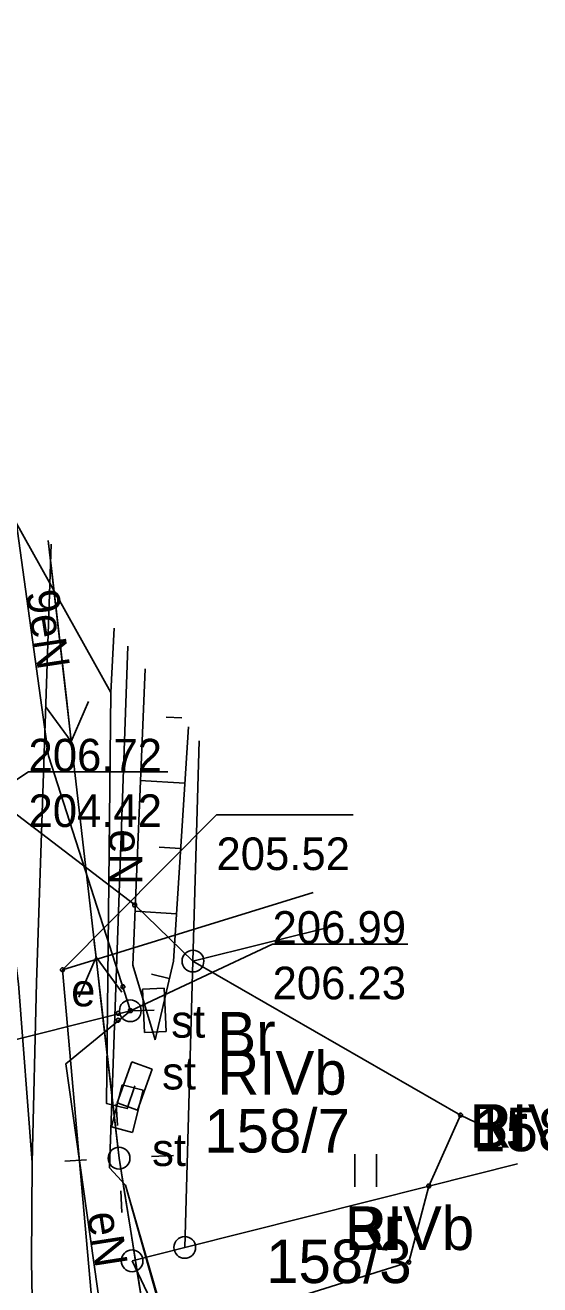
# Model space of a CAD drawing. Extents: x 6512400 to 6513200, y 6022500 to 6022750.
# Drawn here: x 6512853.97 to 6512865.8, y 6022634.38 to 6022663.33 of the extents above; entities that cross this region are included whole.
import ezdxf

# ---------------------------------------------------------------- set-up
doc = ezdxf.new("R2010")
doc.units = 0
for name, color, linetype in [('202-punkt graniczny', 7, 'Continuous'), ('203-punkt graniczny', 7, 'Continuous'), ('209-oznaczenie konturu klasyfikacyjnego', 7, 'Continuous'), ('210-oznaczenie konturu użytku gruntowego', 7, 'Continuous'), ('211-numer działki ewidencyjnej', 7, 'Continuous'), ('217-kontur klasyfikacyjny', 7, 'Continuous'), ('218-kontur użytku gruntowego', 7, 'Continuous'), ('219-działka ewidencyjna', 7, 'Continuous'), ('820-Skarpa nieumocniona', 7, 'Continuous'), ('823-Szczyt skarpy nieumocninej', 7, 'Continuous'), ('824-Podnóże skarpy nieumocninej', 7, 'Continuous'), ('940-Trawnik symb. poj.', 7, 'Continuous'), ('chodnik (powierzchnia)', 7, 'Continuous'), ('krawężnik (linia)', 7, 'Continuous'), ('latarnia na słupie lub maszcie (punkt)', 7, 'Continuous'), ('ogrodzenie trwałe (linia)', 7, 'Continuous'), ('przewód elektroenergetyczny (linia)', 7, 'Continuous'), ('przewód elektroenergetyczny (linia)-Atr1', 7, 'Continuous'), ('przewód elektroenergetyczny niskiego napięcia (linia)', 7, 'Continuous'), ('przewód elektroenergetyczny niskiego napięcia (linia) - symbol', 7, 'Continuous'), ('przewód gazowy (linia)', 7, 'Continuous'), ('punkt o określonej wysokości (sieć ciepłownicza)-Atr2', 7, 'Continuous'), ('punkt o określonej wysokości (sieć ciepłownicza)-Atr3', 7, 'Continuous'), ('punkt o określonej wysokości (sieć elektroenergetyczna)', 7, 'Continuous'), ('punkt o określonej wysokości (sieć elektroenergetyczna)-Atr2', 7, 'Continuous'), ('punkt o określonej wysokości (sieć elektroenergetyczna)-Atr3', 7, 'Continuous'), ('punkt o określonej wysokości (sieć gazowa)', 7, 'Continuous'), ('punkt o określonej wysokości (sieć gazowa)-Atr2', 7, 'Continuous'), ('punkt o określonej wysokości (sieć gazowa)-Atr3', 7, 'Continuous'), ('szafa elektroenergetyczna (punkt)', 7, 'Continuous'), ('szafa elektroenergetyczna (punkt)-Atr17', 7, 'Continuous'), ('słup (punkt)', 7, 'Continuous'), ('właz okrągły - siec elektroenergetyczna (punkt)', 7, 'Continuous'), ('właz okrągły - siec elektroenergetyczna (punkt)-Atr17', 7, 'Continuous')]:
    doc.layers.add(name, color=color, linetype=linetype)

# ---------------------------------------------------------------- blocks, each defined once
blk = doc.blocks.new('203')
blk.add_circle((0, 0), 0.045)
blk = doc.blocks.new('202')
blk.add_circle((0, 0), 0.25)
blk = doc.blocks.new('940P')
for p, q in [((-0.25, -0.375), (-0.25, 0.375)), ((0.25, -0.375), (0.25, 0.375))]:
    blk.add_line(p, q)
blk = doc.blocks.new('US18')
for p, q in [((-0.5, -0.25), (-0.5, 0.25)), ((-0.5, 0.25), (0.5, 0.25)), ((0.5, -0.25), (0.5, 0.25)), ((-0.5, -0.25), (0.5, -0.25))]:
    blk.add_line(p, q)
blk = doc.blocks.new('PW01')
blk.add_circle((0, 0), 0.045)
blk = doc.blocks.new('US22')
blk.add_circle((0, 0), 0.25)
blk = doc.blocks.new('PE04')
for p, q in [((4.65, 0), (3.784, 0.5)), ((0.65, 0), (0, 0)), ((0.65, 0), (1.65, 0)), ((1.65, 0), (2.65, 0)), ((2.65, 0), (3.65, 0)), ((3.65, 0), (4.65, 0)), ((4.65, 0), (3.784, -0.5)), ((4.65, 0), (5, 0))]:
    blk.add_line(p, q)
blk = doc.blocks.new('SM04')
blk.add_circle((0, 0), 0.25)
blk = doc.blocks.new('SM011')
for p, q in [((-0.53, 0.531), (-0.883, 0.884)), ((0.531, 0.531), (0.884, 0.884)), ((-0.53, -0.53), (-0.883, -0.883)), ((0.531, -0.53), (0.884, -0.883))]:
    blk.add_line(p, q)

msp = doc.modelspace()

# ---------------------------------------------------------------- linework, layer by layer
at = {"layer": '217-kontur klasyfikacyjny'}
for points in [[(6512857.83, 6022641.82), (6512857.64, 6022635.24)], [(6512863.98, 6022638.28), (6512857.83, 6022641.82)], [(6512863.98, 6022638.28), (6512863.25, 6022636.65)], [(6512863.25, 6022636.65), (6512863.98, 6022638.28)], [(6512864.702, 6022637.935), (6512863.98, 6022638.28)], [(6512865.286, 6022637.159), (6512863.25, 6022636.65)], [(6512863.25, 6022636.65), (6512865.286, 6022637.159)], [(6512863.25, 6022636.65), (6512857.64, 6022635.24)], [(6512857.64, 6022635.24), (6512863.25, 6022636.65)], [(6512863.25, 6022636.65), (6512862.79, 6022634.9)], [(6512862.79, 6022634.9), (6512863.25, 6022636.65)], [(6512857.64, 6022635.24), (6512856.43, 6022634.93)], [(6512856.43, 6022634.93), (6512857.27, 6022633.17)], [(6512862.79, 6022634.9), (6512857.27, 6022633.17)], [(6512857.27, 6022633.17), (6512862.79, 6022634.9)]]:
    msp.add_lwpolyline(points, dxfattribs=at)
at = {"layer": '218-kontur użytku gruntowego'}
for points in [[(6512838.55, 6022656.82), (6512856.49, 6022643.11)], [(6512856.49, 6022643.11), (6512838.55, 6022656.82)], [(6512857.83, 6022641.82), (6512857.969, 6022646.885)], [(6512857.969, 6022646.885), (6512857.83, 6022641.82)], [(6512856.49, 6022643.11), (6512857.83, 6022641.82)], [(6512857.83, 6022641.82), (6512856.49, 6022643.11)], [(6512857.64, 6022635.24), (6512857.83, 6022641.82)], [(6512857.83, 6022641.82), (6512857.64, 6022635.24)], [(6512863.98, 6022638.28), (6512857.83, 6022641.82)], [(6512857.83, 6022641.82), (6512863.98, 6022638.28)], [(6512863.98, 6022638.28), (6512863.25, 6022636.65)], [(6512863.25, 6022636.65), (6512863.98, 6022638.28)], [(6512864.702, 6022637.935), (6512863.98, 6022638.28)], [(6512863.98, 6022638.28), (6512864.702, 6022637.935)], [(6512865.286, 6022637.159), (6512863.25, 6022636.65)], [(6512863.25, 6022636.65), (6512865.286, 6022637.159)], [(6512863.25, 6022636.65), (6512857.64, 6022635.24)], [(6512857.64, 6022635.24), (6512863.25, 6022636.65)], [(6512863.25, 6022636.65), (6512862.79, 6022634.9)], [(6512862.79, 6022634.9), (6512863.25, 6022636.65)], [(6512856.43, 6022634.93), (6512857.64, 6022635.24)], [(6512857.64, 6022635.24), (6512856.43, 6022634.93)], [(6512857.27, 6022633.17), (6512856.43, 6022634.93)], [(6512856.43, 6022634.93), (6512857.27, 6022633.17)], [(6512862.79, 6022634.9), (6512857.27, 6022633.17)], [(6512857.27, 6022633.17), (6512862.79, 6022634.9)]]:
    msp.add_lwpolyline(points, dxfattribs=at)
at = {"layer": '219-działka ewidencyjna'}
for points in [[(6512856.49, 6022643.11), (6512838.55, 6022656.82)], [(6512857.83, 6022641.82), (6512857.969, 6022646.885)], [(6512857.83, 6022641.82), (6512856.49, 6022643.11)], [(6512857.83, 6022641.82), (6512861.155, 6022642.649)], [(6512857.83, 6022641.82), (6512857.64, 6022635.24)], [(6512863.98, 6022638.28), (6512857.83, 6022641.82)], [(6512863.98, 6022638.28), (6512863.25, 6022636.65)], [(6512864.702, 6022637.935), (6512863.98, 6022638.28)], [(6512865.286, 6022637.159), (6512863.25, 6022636.65)], [(6512863.25, 6022636.65), (6512857.64, 6022635.24)], [(6512863.25, 6022636.65), (6512862.79, 6022634.9)], [(6512856.43, 6022634.93), (6512857.64, 6022635.24)], [(6512857.27, 6022633.17), (6512856.43, 6022634.93)], [(6512862.79, 6022634.9), (6512857.27, 6022633.17)]]:
    msp.add_lwpolyline(points, dxfattribs=at)
at = {"layer": '820-Skarpa nieumocniona'}
for p, q in [((6512857.575, 6022647.409), (6512857.21, 6022647.43)), ((6512857.64, 6022645.91), (6512856.61, 6022645.97)), ((6512857.54, 6022644.41), (6512857.05, 6022644.44)), ((6512857.45, 6022642.91), (6512856.49, 6022642.97)), ((6512857.28, 6022641.42), (6512856.88, 6022641.52))]:
    msp.add_line(p, q, dxfattribs=at)
at = {"layer": '823-Szczyt skarpy nieumocninej'}
msp.add_lwpolyline([(6512857.727, 6022647.206), (6512857.38, 6022641.82), (6512856.96, 6022640.01)], dxfattribs=at)
at = {"layer": '824-Podnóże skarpy nieumocninej'}
msp.add_lwpolyline([(6512856.728, 6022648.534), (6512856.45, 6022641.73), (6512856.96, 6022640.01)], dxfattribs=at)
at = {"layer": 'chodnik (powierzchnia)'}
for points in [[(6512852.028, 6022654.782), (6512852.46, 6022651.24), (6512853.17, 6022646.34), (6512853.82, 6022641.3), (6512854.13, 6022637.19), (6512854.23, 6022641.33)], [(6512854.23, 6022641.33), (6512854.572, 6022651.4)], [(6512856.331, 6022649.061), (6512855.91, 6022637.07), (6512856.28, 6022636.67), (6512857.18, 6022633.47)]]:
    msp.add_lwpolyline(points, dxfattribs=at)
at = {"layer": 'krawężnik (linia)'}
msp.add_lwpolyline([(6512854.13, 6022634.06), (6512854.12, 6022634.93), (6512854.13, 6022637.19), (6512853.82, 6022641.3), (6512853.17, 6022646.34), (6512852.46, 6022651.24), (6512852.028, 6022654.782)], dxfattribs=at)
at = {"layer": 'ogrodzenie trwałe (linia)'}
msp.add_lwpolyline([(6512859.49, 6022628.57), (6512858.5, 6022630.69), (6512857.21, 6022633.44), (6512856.28, 6022636.67)], dxfattribs=at)
at = {"layer": 'przewód elektroenergetyczny (linia)'}
for points in [[(6512856.32, 6022638.43), (6512855.84, 6022638.55), (6512855.94, 6022647.99), (6512853.31, 6022652.69), (6512841.05, 6022650.73), (6512840.36, 6022658.31), (6512832.38, 6022663.33)], [(6512856.39, 6022640.68), (6512854.51, 6022646.54), (6512853.677, 6022652.59)], [(6512856.022, 6022649.473), (6512855.94, 6022647.99), (6512855.84, 6022638.55), (6512856.32, 6022638.43), (6512856.49, 6022638.95)], [(6512856.39, 6022640.68), (6512852.99, 6022639.83), (6512851.54, 6022639.74), (6512850.48, 6022647.67), (6512851.95, 6022647.83), (6512852.99, 6022639.83)], [(6512856.39, 6022640.68), (6512852.99, 6022639.83), (6512851.54, 6022639.74), (6512849.57, 6022639.5), (6512850.08, 6022635.56), (6512848.6, 6022635.43), (6512846.66, 6022647.32), (6512848.47, 6022647.49), (6512849.57, 6022639.5)], [(6512856.39, 6022640.68), (6512854.91, 6022639.46), (6512857.58, 6022620.49)], [(6512856.39, 6022640.68), (6512856.94, 6022640.69)]]:
    msp.add_lwpolyline(points, dxfattribs=at)
at = {"layer": 'przewód elektroenergetyczny niskiego napięcia (linia)'}
for points in [[(6512856.13, 6022637.29), (6512854.505, 6022651.489)], [(6512854.505, 6022651.489), (6512856.13, 6022637.29)], [(6512861.56, 6022603.29), (6512856.13, 6022637.29)]]:
    msp.add_lwpolyline(points, dxfattribs=at)
at = {"layer": 'przewód gazowy (linia)'}
for points in [[(6512854.83, 6022641.62), (6512860.596, 6022643.393)], [(6512871.862, 6022571.535), (6512870.29, 6022578.43), (6512869.58, 6022581.52), (6512865.64, 6022595.96), (6512860.06, 6022617.51), (6512858.39, 6022625.33), (6512855.49, 6022634.19), (6512854.83, 6022641.62)]]:
    msp.add_lwpolyline(points, dxfattribs=at)
at = {"layer": 'punkt o określonej wysokości (sieć ciepłownicza)-Atr2'}
msp.add_lwpolyline([(6512851.41, 6022644.43), (6512854.05, 6022646.17), (6512857.254, 6022646.17)], dxfattribs=at)
at = {"layer": 'punkt o określonej wysokości (sieć elektroenergetyczna)-Atr2'}
msp.add_lwpolyline([(6512856.39, 6022640.68), (6512859.66, 6022642.21), (6512862.769, 6022642.21)], dxfattribs=at)
at = {"layer": 'punkt o określonej wysokości (sieć gazowa)-Atr2'}
msp.add_lwpolyline([(6512854.83, 6022641.62), (6512858.37, 6022645.18), (6512861.511, 6022645.18)], dxfattribs=at)

# ---------------------------------------------------------------- block references
at = {"layer": '202-punkt graniczny'}
for p in [(6512857.83, 6022641.82), (6512857.64, 6022635.24), (6512856.43, 6022634.93)]:
    msp.add_blockref('202', p, dxfattribs=at)
at = {"layer": '203-punkt graniczny'}
for p in [(6512856.49, 6022643.11), (6512863.98, 6022638.28), (6512863.25, 6022636.65), (6512862.79, 6022634.9)]:
    msp.add_blockref('203', p, dxfattribs=at)
at = {"layer": '940-Trawnik symb. poj.', "rotation": 180}
msp.add_blockref('940P', (6512861.8, 6022637.01), dxfattribs=at)
at = {"layer": 'latarnia na słupie lub maszcie (punkt)', "rotation": -42.018}
msp.add_blockref('SM011', (6512856.13, 6022637.29), dxfattribs=at)
at = {"layer": 'przewód elektroenergetyczny niskiego napięcia (linia) - symbol'}
for p, rotation in [((6512854.505, 6022651.489), -83.47099999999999), ((6512856.13, 6022637.29), 96.529), ((6512856.13, 6022637.29), -80.92599999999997)]:
    msp.add_blockref('PE04', p, dxfattribs=dict(at, rotation=rotation))
at = {"layer": 'punkt o określonej wysokości (sieć elektroenergetyczna)'}
for p, rotation in [((6512856.22, 6022641.23), -71.418), ((6512856.39, 6022640.68), -90), ((6512856.11, 6022640.46), 40.342), ((6512856.11, 6022640.62), 14.868)]:
    msp.add_blockref('PW01', p, dxfattribs=dict(at, rotation=rotation))
at = {"layer": 'punkt o określonej wysokości (sieć gazowa)'}
msp.add_blockref('PW01', (6512854.83, 6022641.62), dxfattribs=at)
at = {"layer": 'szafa elektroenergetyczna (punkt)'}
for p, rotation in [((6512856.94, 6022640.69), 92.726), ((6512856.49, 6022638.95), 70.34600000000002), ((6512856.32, 6022638.43), -104.381)]:
    msp.add_blockref('US18', p, dxfattribs=dict(at, rotation=rotation))
at = {"layer": 'słup (punkt)'}
msp.add_blockref('SM04', (6512856.13, 6022637.29), dxfattribs=at)
at = {"layer": 'właz okrągły - siec elektroenergetyczna (punkt)', "rotation": -90}
msp.add_blockref('US22', (6512856.39, 6022640.68), dxfattribs=at)

# ---------------------------------------------------------------- texts
at = {"layer": '209-oznaczenie konturu klasyfikacyjnego'}
for p in [(6512858.39, 6022638.75), (6512864.19, 6022637.53), (6512861.32, 6022635.18)]:
    msp.add_text('RIVb', height=1, dxfattribs=at).set_placement(p)
at = {"layer": '210-oznaczenie konturu użytku gruntowego'}
for p in [(6512858.39, 6022639.65), (6512864.19, 6022637.53), (6512861.32, 6022635.18)]:
    msp.add_text('Br', height=1, dxfattribs=at).set_placement(p)
at = {"layer": '211-numer działki ewidencyjnej'}
for s, p in [('158/7', (6512858.09, 6022637.42)), ('158/2', (6512864.27, 6022637.45)), ('158/3', (6512859.51, 6022634.42))]:
    msp.add_text(s, height=1, dxfattribs=at).set_placement(p)
at = {"layer": 'przewód elektroenergetyczny (linia)-Atr1'}
for s, rotation, p in [('9eN', 278.639, (6512853.99, 6022650.3)), ('eN', 270.182, (6512855.91, 6022644.85)), ('eN', 278.799, (6512855.4, 6022636.01))]:
    msp.add_text(s, height=0.75, rotation=rotation, dxfattribs=at).set_placement(p)
at = {"layer": 'punkt o określonej wysokości (sieć ciepłownicza)-Atr2'}
msp.add_text('206.72', height=0.75, dxfattribs=at).set_placement((6512854.05, 6022646.178))
at = {"layer": 'punkt o określonej wysokości (sieć ciepłownicza)-Atr3'}
msp.add_text('204.42', height=0.75, dxfattribs=at).set_placement((6512854.05, 6022644.902))
at = {"layer": 'punkt o określonej wysokości (sieć elektroenergetyczna)-Atr2'}
msp.add_text('206.99', height=0.75, dxfattribs=at).set_placement((6512859.66, 6022642.218))
at = {"layer": 'punkt o określonej wysokości (sieć elektroenergetyczna)-Atr3'}
msp.add_text('206.23', height=0.75, dxfattribs=at).set_placement((6512859.66, 6022640.942))
at = {"layer": 'punkt o określonej wysokości (sieć gazowa)-Atr3'}
msp.add_text('205.52', height=0.75, dxfattribs=at).set_placement((6512858.37, 6022643.912))
at = {"layer": 'szafa elektroenergetyczna (punkt)-Atr17'}
for p in [(6512857.33, 6022640.06), (6512857.12, 6022638.87), (6512856.89, 6022637.11)]:
    msp.add_text('st', height=0.75, dxfattribs=at).set_placement(p)
at = {"layer": 'właz okrągły - siec elektroenergetyczna (punkt)-Atr17'}
msp.add_text('e', height=0.75, dxfattribs=at).set_placement((6512855.03, 6022640.78))

doc.saveas('drawing.dxf')
